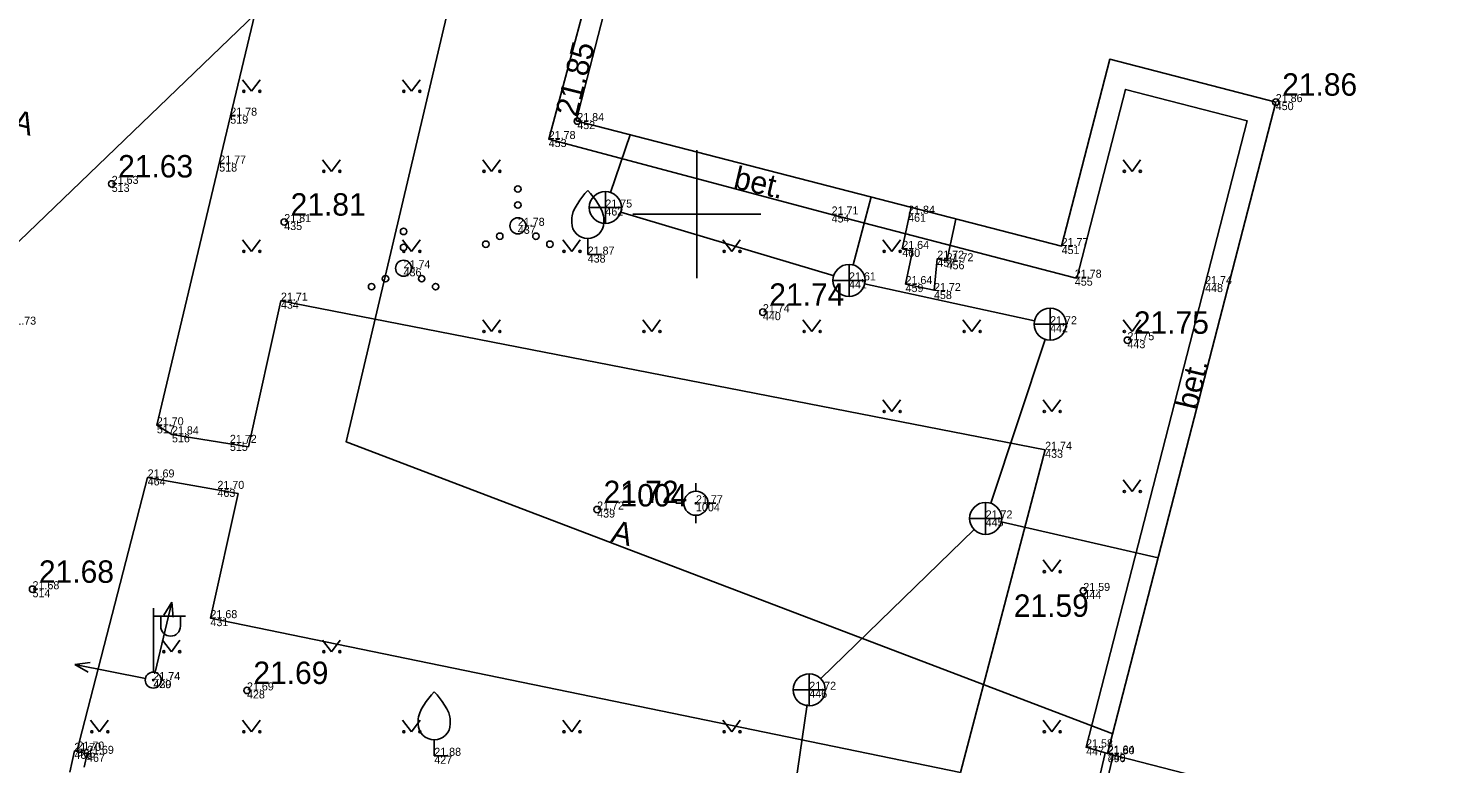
# Model space of a CAD drawing. Extents: x 714279 to 714471, y 6589851 to 6590083.
# Drawn here: x 714329.12 to 714372.9, y 6589982.83 to 6590005.81 of the extents above; entities that cross this region are included whole.
import ezdxf

# ---------------------------------------------------------------- set-up
doc = ezdxf.new("R2010")
doc.units = 0
for name, color, linetype in [('AED', 7, 'Continuous'), ('ALUSVORK', 7, 'Continuous'), ('HALJASTUS', 7, 'Continuous'), ('HOONE', 7, 'Continuous'), ('KKAEV', 7, 'Continuous'), ('KORGUS', 7, 'Continuous'), ('KTRASS', 7, 'Continuous'), ('MOOTKORG', 7, 'Continuous'), ('MOOTMPUNKT', 7, 'Continuous'), ('MPOHULIIN', 7, 'Continuous'), ('POST', 7, 'Continuous'), ('PUU', 7, 'Continuous'), ('SKTRASS', 7, 'Continuous'), ('TEE', 7, 'Continuous'), ('TTRASS', 7, 'Continuous'), ('VORK', 7, 'Continuous')]:
    doc.layers.add(name, color=color, linetype=linetype)

# ---------------------------------------------------------------- blocks, each defined once
blk = doc.blocks.new('SPYMAR')
at = {"layer": 'ALUSVORK'}
for p, q in [((0, 0.75), (0, 1.25)), ((-0.75, 0), (-1.25, 0)), ((0.75, 0), (1.25, 0)), ((0, -0.75), (0, -1.25))]:
    blk.add_line(p, q, dxfattribs=at)
for radius in [0.75, 0.044]:
    blk.add_circle((0, 0), radius, dxfattribs=at)
blk = doc.blocks.new('VILJA1')
at = {"layer": 'PUU'}
for p, q in [((0, 0), (0, 1)), ((0.8, 0), (0, 0))]:
    blk.add_line(p, q, dxfattribs=at)
for points in [[(-1, 2), (-1, 2.3), (-0.98, 2.43), (-0.91, 2.69), (-0.79, 2.93), (-0.5, 3.4), (-0.18, 3.81), (0, 4)], [(1, 2), (1, 2.3), (0.98, 2.43), (0.91, 2.69), (0.79, 2.93), (0.5, 3.4), (0.18, 3.81), (0, 4)]]:
    blk.add_lwpolyline(points, dxfattribs=at)
blk.add_arc((0, 2), 1, 180, 0, dxfattribs=at)
blk = doc.blocks.new('RING02')
at = {"layer": 'KORGUS'}
blk.add_circle((0, 0), 0.2, dxfattribs=at)
blk = doc.blocks.new('BEPOST')
at = {"layer": 'POST'}
for radius in [0.5, 0.0467]:
    blk.add_circle((0, 0), radius, dxfattribs=at)
blk = doc.blocks.new('POINT_DISPLAY')
blk.add_line((0, 0), (0, 0))
blk = doc.blocks.new('VAPOST')
at = {"layer": 'POST'}
for p, q in [((0, 0.5), (0, 4.5)), ((0, 4), (2, 4)), ((0.453, 3.358), (0.453, 4)), ((1.679, 3.358), (1.679, 4))]:
    blk.add_line(p, q, dxfattribs=at)
blk.add_arc((1.066, 3.358), 0.613, 180, 0, dxfattribs=at)
blk.add_blockref('POINT_DISPLAY', (0, 0), dxfattribs=at)
blk = doc.blocks.new('VQSA')
at = {"layer": 'HALJASTUS'}
for centre, radius in [((0, 2.3), 0.2), ((0, 1.3), 0.2), ((0, 0), 0.5), ((-1.13, -0.65), 0.2), ((1.13, -0.65), 0.2), ((-2, -1.15), 0.2), ((2, -1.15), 0.2)]:
    blk.add_circle(centre, radius, dxfattribs=at)
blk = doc.blocks.new('KAKAEV')
at = {"layer": 'KKAEV'}
for p, q in [((0, -1), (0, 1)), ((-1, 0), (1, 0))]:
    blk.add_line(p, q, dxfattribs=at)
blk.add_circle((0, 0), 1, dxfattribs=at)
blk = doc.blocks.new('MPSUUN')
at = {"layer": 'MPOHULIIN'}
for p, q in [((0.5, 0), (5, 0)), ((5, 0), (4.097, -0.297)), ((5, 0), (4.098, 0.3))]:
    blk.add_line(p, q, dxfattribs=at)
blk.add_blockref('POINT_DISPLAY', (0, 0), dxfattribs=at)
blk = doc.blocks.new('MURU_1')
at = {"layer": 'HALJASTUS'}
for p, q in [((-0.93, 1.21), (0, 0)), ((0, 0), (0.89, 1.21))]:
    blk.add_line(p, q, dxfattribs=at)
for centre in [(-0.8, 0), (0.86, 0)]:
    blk.add_circle(centre, 0.11, dxfattribs=at)

msp = doc.modelspace()

# ---------------------------------------------------------------- linework, layer by layer
at = {"layer": 'AED'}
for points in [[(714330.419, 6589982.569), (714330.563, 6589983.236), (714330.959, 6589983.144), (714330.874, 6589982.731)], [(714361.258, 6589976.716), (714362.749, 6589983.12), (714362.761, 6589983.17), (714362.833, 6589983.153)], [(714363.003, 6589983.109), (714362.992, 6589983.063), (714361.448, 6589976.429)]]:
    msp.add_lwpolyline(points, dxfattribs=at)
at = {"layer": 'HOONE'}
for points in [[(714368.084, 6590003.497), (714362.833, 6589983.153), (714366.948, 6589982.091), (714366.479, 6589980.273), (714368.704, 6589979.699), (714369.168, 6589981.497), (714375.054, 6589979.978), (714385.707, 6590021.254), (714379.88, 6590022.758), (714380.346, 6590024.563), (714378.09, 6590025.145), (714377.63, 6590023.366), (714373.521, 6590024.426), (714369.05, 6590007.103), (714363.815, 6590008.455), (714364.534, 6590011.243), (714349.394, 6590015.151), (714346.235, 6590002.913), (714361.396, 6589999), (714362.901, 6590004.835), (714368.084, 6590003.497)], [(714356.7, 6590000.212), (714356.42, 6589998.912), (714356.744, 6589998.842), (714356.522, 6589997.814), (714357.415, 6589997.621), (714357.512, 6589998.607), (714357.808, 6589998.543), (714358.088, 6589999.844)]]:
    msp.add_lwpolyline(points, dxfattribs=at)
at = {"layer": 'KORGUS'}
for centre in [(714368.084, 6590003.497), (714346.27, 6590002.904)]:
    msp.add_circle(centre, 0.1, dxfattribs=at)
at = {"layer": 'KTRASS'}
for points in [[(714347.308, 6590000.677), (714347.925, 6590002.477)], [(714354.885, 6589998.412), (714355.452, 6590000.535)], [(714347.628, 6590000.06), (714354.291, 6589998.068)], [(714360.55, 6589996.667), (714355.24, 6589997.824)], [(714359.181, 6589990.969), (714360.881, 6589996.087)], [(714353.873, 6589985.492), (714358.666, 6589990.148)], [(714359.508, 6589990.386), (714364.411, 6589989.266)], [(714352.31, 6589976.898), (714353.447, 6589984.68)]]:
    msp.add_lwpolyline(points, dxfattribs=at)
at = {"layer": 'SKTRASS'}
msp.add_lwpolyline([(714320.65, 6589991.283), (714354.787, 6590024.118)], dxfattribs=at)
at = {"layer": 'TEE'}
for points in [[(714336.001, 6589992.726), (714333.612, 6589993.121), (714333.139, 6589993.403), (714335.261, 6590002.325), (714339.537, 6590020.216)], [(714361.809, 6589998.014), (714354.213, 6589999.987), (714345.378, 6590002.344), (714347.181, 6590009.051)], [(714365.878, 6589997.813), (714367.189, 6590002.915), (714363.389, 6590003.891), (714361.875, 6589997.997), (714361.809, 6589998.014)], [(714365.878, 6589997.813), (714362.162, 6589983.348), (714362.833, 6589983.153)], [(714336.001, 6589992.726), (714337.015, 6589997.295), (714360.881, 6589992.639), (714358.236, 6589982.565), (714334.814, 6589987.381), (714335.678, 6589991.274)], [(714335.678, 6589991.274), (714332.852, 6589991.776), (714330.642, 6589983.218)]]:
    msp.add_lwpolyline(points, dxfattribs=at)
at = {"layer": 'TTRASS'}
msp.add_lwpolyline([(714346.146, 6590022.954), (714339.047, 6589992.888), (714362.991, 6589983.765)], dxfattribs=at)
at = {"layer": 'VORK'}
for p, q in [((714350, 6590002), (714350, 6589998)), ((714348, 6590000), (714352, 6590000))]:
    msp.add_line(p, q, dxfattribs=at)

# ---------------------------------------------------------------- block references
at = {"layer": 'ALUSVORK', "xscale": 0.5, "yscale": 0.5}
msp.add_blockref('SPYMAR', (714349.976, 6589990.968), dxfattribs=at)
at = {"layer": 'HALJASTUS'}
for name, p, xscale, yscale in [('MURU_1', (714336.095, 6590003.834), 0.3, 0.3), ('MURU_1', (714341.095, 6590003.834), 0.3, 0.3), ('MURU_1', (714338.595, 6590001.334), 0.3, 0.3), ('MURU_1', (714343.595, 6590001.334), 0.3, 0.3), ('MURU_1', (714363.595, 6590001.334), 0.3, 0.3), ('VQSA', (714344.414, 6589999.633), 0.5, 0.5), ('VQSA', (714340.845, 6589998.307), 0.5, 0.5), ('MURU_1', (714336.095, 6589998.834), 0.3, 0.3), ('MURU_1', (714341.095, 6589998.834), 0.3, 0.3), ('MURU_1', (714346.095, 6589998.834), 0.3, 0.3), ('MURU_1', (714351.095, 6589998.834), 0.3, 0.3), ('MURU_1', (714356.095, 6589998.834), 0.3, 0.3), ('MURU_1', (714343.595, 6589996.334), 0.3, 0.3), ('MURU_1', (714348.595, 6589996.334), 0.3, 0.3), ('MURU_1', (714353.595, 6589996.334), 0.3, 0.3), ('MURU_1', (714358.595, 6589996.334), 0.3, 0.3), ('MURU_1', (714363.595, 6589996.334), 0.3, 0.3), ('MURU_1', (714356.095, 6589993.834), 0.3, 0.3), ('MURU_1', (714361.095, 6589993.834), 0.3, 0.3), ('MURU_1', (714363.595, 6589991.334), 0.3, 0.3), ('MURU_1', (714361.095, 6589988.834), 0.3, 0.3), ('MURU_1', (714333.595, 6589986.334), 0.3, 0.3), ('MURU_1', (714338.595, 6589986.334), 0.3, 0.3), ('MURU_1', (714331.351, 6589983.834), 0.3, 0.3), ('MURU_1', (714336.095, 6589983.834), 0.3, 0.3), ('MURU_1', (714341.095, 6589983.834), 0.3, 0.3), ('MURU_1', (714346.095, 6589983.834), 0.3, 0.3), ('MURU_1', (714351.095, 6589983.834), 0.3, 0.3), ('MURU_1', (714361.095, 6589983.834), 0.3, 0.3)]:
    msp.add_blockref(name, p, dxfattribs=dict(at, xscale=xscale, yscale=yscale))
at = {"layer": 'KKAEV', "xscale": 0.5, "yscale": 0.5}
for p in [(714347.146, 6590000.204), (714354.756, 6589997.929), (714361.038, 6589996.561), (714359.024, 6589990.496), (714353.515, 6589985.144)]:
    msp.add_blockref('KAKAEV', p, dxfattribs=at)
at = {"layer": 'KORGUS', "xscale": 0.5, "yscale": 0.5}
for p in [(714331.73, 6590000.943), (714337.118, 6589999.751), (714352.067, 6589996.936), (714363.453, 6589996.061), (714346.891, 6589990.772), (714329.257, 6589988.284), (714362.073, 6589988.231), (714335.954, 6589985.124)]:
    msp.add_blockref('RING02', p, dxfattribs=at)
at = {"layer": 'MPOHULIIN', "xscale": 0.5, "yscale": 0.5}
for rotation in [76.84360216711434, 168.76823361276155]:
    msp.add_blockref('MPSUUN', (714333.035, 6589985.447), dxfattribs=dict(at, rotation=rotation))
at = {"layer": 'POST', "xscale": 0.5, "yscale": 0.5}
for name, p in [('VAPOST', (714333.035, 6589985.447)), ('BEPOST', (714333.028, 6589985.446))]:
    msp.add_blockref(name, p, dxfattribs=at)
at = {"layer": 'PUU', "xscale": 0.5, "yscale": 0.5}
for p in [(714346.595, 6589998.735), (714341.803, 6589983.082)]:
    msp.add_blockref('VILJA1', p, dxfattribs=at)

# ---------------------------------------------------------------- texts
at = {"layer": 'ALUSVORK'}
msp.add_text('1004', height=0.7, dxfattribs=at).set_placement((714347.619, 6589990.868))
at = {"layer": 'KORGUS'}
msp.add_text('21.85', height=0.7, rotation=76.0927, dxfattribs=at).set_placement((714346.256, 6590003.002))
for s, p in [('21.86', (714368.284, 6590003.697)), ('21.63', (714331.93, 6590001.143)), ('21.81', (714337.318, 6589999.951)), ('21.74', (714352.267, 6589997.136)), ('21.75', (714363.653, 6589996.261)), ('21.72', (714347.091, 6589990.972)), ('21.68', (714329.457, 6589988.484)), ('21.59', (714359.903, 6589987.422)), ('21.69', (714336.154, 6589985.324))]:
    msp.add_text(s, height=0.7, dxfattribs=at).set_placement(p)
at = {"layer": 'MOOTKORG'}
for s, p in [('21.86', (714368.084, 6590003.497)), ('21.78', (714335.433, 6590003.073)), ('21.84', (714346.27, 6590002.904)), ('21.78', (714345.378, 6590002.344)), ('21.77', (714335.088, 6590001.578)), ('21.63', (714331.73, 6590000.943)), ('21.75', (714347.146, 6590000.204)), ('21.71', (714354.213, 6589999.987)), ('21.84', (714356.603, 6590000.011)), ('21.81', (714337.118, 6589999.751)), ('21.78', (714344.414, 6589999.633)), ('21.87', (714346.595, 6589998.735)), ('21.64', (714356.42, 6589998.912)), ('21.77', (714361.396, 6589999.002)), ('21.74', (714340.845, 6589998.307)), ('21.72', (714357.512, 6589998.607)), ('21.72', (714357.804, 6589998.527)), ('21.61', (714354.756, 6589997.929)), ('21.64', (714356.522, 6589997.814)), ('21.78', (714361.809, 6589998.014)), ('21.74', (714365.878, 6589997.813)), ('21.72', (714357.41, 6589997.597)), ('21.71', (714337.015, 6589997.295)), ('21.74', (714352.067, 6589996.936)), ('21.73', (714328.532, 6589996.547)), ('21.72', (714361.038, 6589996.561)), ('21.75', (714363.453, 6589996.061)), ('21.70', (714333.139, 6589993.403)), ('21.84', (714333.612, 6589993.121)), ('21.72', (714335.421, 6589992.855)), ('21.74', (714360.881, 6589992.639)), ('21.69', (714332.852, 6589991.776)), ('21.70', (714335.032, 6589991.418)), ('21.72', (714346.891, 6589990.772)), ('21.77', (714349.976, 6589990.968)), ('21.72', (714359.024, 6589990.496)), ('21.68', (714329.257, 6589988.284)), ('21.59', (714362.073, 6589988.231)), ('21.68', (714334.814, 6589987.381)), ('21.74', (714333.028, 6589985.446)), ('21.74', (714333.035, 6589985.447)), ('21.69', (714335.954, 6589985.124)), ('21.72', (714353.515, 6589985.144)), ('21.58', (714362.162, 6589983.348)), ('21.70', (714330.563, 6589983.236)), ('21.70', (714330.659, 6589983.277)), ('21.69', (714330.959, 6589983.144)), ('21.88', (714341.803, 6589983.082)), ('21.64', (714362.833, 6589983.153)), ('21.80', (714362.837, 6589983.133))]:
    msp.add_text(s, height=0.25, dxfattribs=at).set_placement(p)
at = {"layer": 'MOOTMPUNKT'}
for s, p in [('450', (714368.084, 6590003.247)), ('519', (714335.433, 6590002.823)), ('452', (714346.27, 6590002.654)), ('453', (714345.378, 6590002.094)), ('518', (714335.088, 6590001.328)), ('513', (714331.73, 6590000.693)), ('462', (714347.146, 6589999.954)), ('454', (714354.213, 6589999.737)), ('461', (714356.603, 6589999.761)), ('435', (714337.118, 6589999.501)), ('437', (714344.414, 6589999.383)), ('460', (714356.42, 6589998.662)), ('451', (714361.396, 6589998.752)), ('438', (714346.595, 6589998.485)), ('457', (714357.512, 6589998.357)), ('456', (714357.804, 6589998.277)), ('436', (714340.845, 6589998.057)), ('441', (714354.756, 6589997.679)), ('459', (714356.522, 6589997.564)), ('458', (714357.41, 6589997.347)), ('455', (714361.809, 6589997.764)), ('448', (714365.878, 6589997.563)), ('434', (714337.015, 6589997.045)), ('440', (714352.067, 6589996.686)), ('442', (714361.038, 6589996.311)), ('443', (714363.453, 6589995.811)), ('517', (714333.139, 6589993.153)), ('516', (714333.612, 6589992.871)), ('515', (714335.421, 6589992.605)), ('433', (714360.881, 6589992.389)), ('464', (714332.852, 6589991.526)), ('463', (714335.032, 6589991.168)), ('439', (714346.891, 6589990.522)), ('1004', (714349.976, 6589990.718)), ('445', (714359.024, 6589990.246)), ('514', (714329.257, 6589988.034)), ('444', (714362.073, 6589987.981)), ('431', (714334.814, 6589987.131)), ('429', (714333.028, 6589985.196)), ('430', (714333.035, 6589985.197)), ('428', (714335.954, 6589984.874)), ('446', (714353.515, 6589984.894)), ('466', (714330.563, 6589982.986)), ('465', (714330.659, 6589983.027)), ('467', (714330.959, 6589982.894)), ('447', (714362.162, 6589983.098)), ('449', (714362.833, 6589982.903)), ('427', (714341.803, 6589982.832)), ('390', (714362.837, 6589982.883))]:
    msp.add_text(s, height=0.25, dxfattribs=at).set_placement(p)
at = {"layer": 'TEE'}
for s, rotation, p in [('A', 345.7136, (714328.583, 6590002.596)), ('bet.', 346.9398, (714351.115, 6590000.821)), ('bet.', 76.6125, (714365.623, 6589993.853)), ('A', 346.3944, (714347.289, 6589989.774))]:
    msp.add_text(s, height=0.7, rotation=rotation, dxfattribs=at).set_placement(p)

doc.saveas('drawing.dxf')
